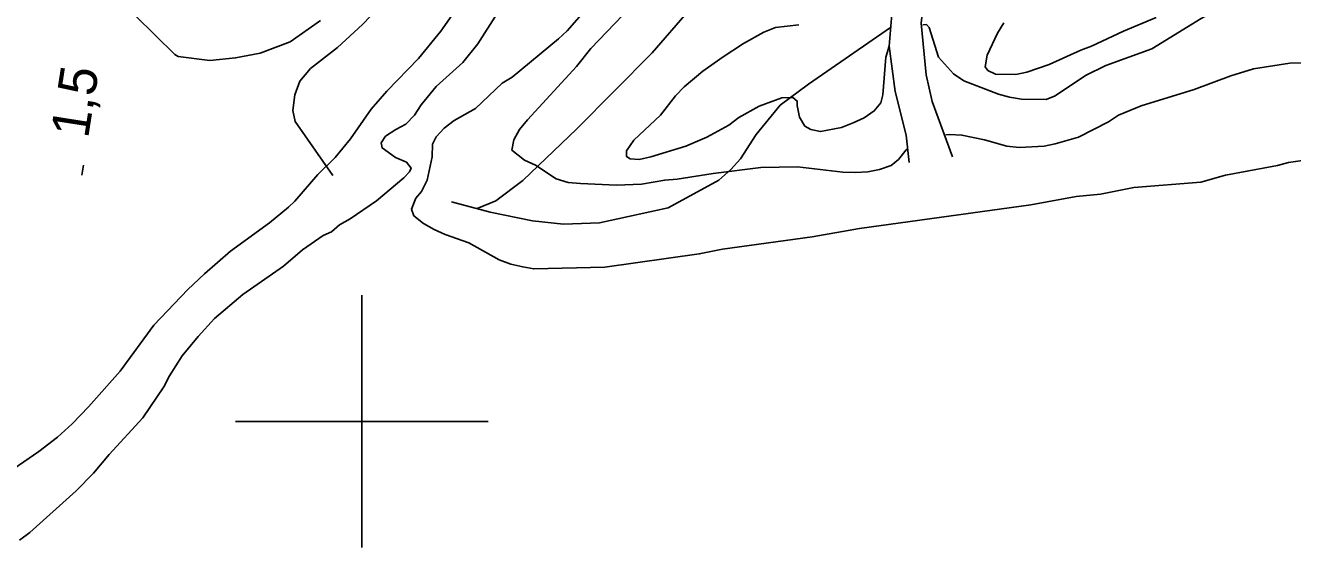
# Model space of a CAD drawing. Extents: x 282461 to 284471, y 5554090 to 5557646.
# Drawn here: x 282973.4 to 283073.7, y 5554590 to 5554631.3 of the extents above; entities that cross this region are included whole.
import ezdxf

# ---------------------------------------------------------------- set-up
doc = ezdxf.new("R2010")
doc.units = 0
for name, color, linetype in [('Niveau 19', 7, 'Continuous'), ('Niveau 2', 7, 'Continuous'), ('Niveau 22', 7, 'Continuous'), ('Niveau 3', 7, 'Continuous'), ('Niveau 4', 7, 'Continuous'), ('Niveau 61', 7, 'Continuous')]:
    doc.layers.add(name, color=color, linetype=linetype)

msp = doc.modelspace()

# ---------------------------------------------------------------- linework, layer by layer
at = {"layer": 'Niveau 19'}
for points in [[(283068.06, 5554712.51), (283063.46, 5554707.21), (283055.84, 5554697.45), (283052.31, 5554692.63), (283048.44, 5554688.04), (283043.95, 5554683.22), (283041.39, 5554680.04), (283038.21, 5554675.64), (283035.71, 5554672.46), (283032.03, 5554667.89), (283028.04, 5554663.47), (283020.37, 5554653.48), (283012.4, 5554644.31), (283000.04, 5554631.42), (282998.06, 5554629.6), (282995.94, 5554627.94), (282995.09, 5554626.94), (282994.7, 5554625.84), (282994.55, 5554624.62), (282994.72, 5554623.73), (282997.7, 5554619.47)], [(283103.3, 5554710.23), (283094.06, 5554697.21), (283089.32, 5554691.96), (283085.62, 5554687.44), (283080.84, 5554681.32), (283077.36, 5554677.32), (283075.87, 5554675.79), (283069.49, 5554668.61), (283064.87, 5554664.36), (283060.8, 5554660.17), (283053.44, 5554652.98), (283049.9, 5554649.91), (283046.8, 5554647), (283044.52, 5554644.42), (283043.56, 5554642.72), (283042.42, 5554637.95), (283041.73, 5554629.69), (283042.2, 5554626.11), (283043.06, 5554622.65), (283043.31, 5554620.49)], [(283046.73, 5554620.95), (283045.12, 5554625.31), (283044.66, 5554627.42), (283044.25, 5554631.52), (283044.78, 5554636.43), (283045.42, 5554638.98), (283045.97, 5554640.73), (283046.75, 5554642.6), (283049.01, 5554646.11), (283053.42, 5554650.48), (283056.64, 5554653.39), (283060.57, 5554656.74), (283066.45, 5554662.75), (283069.43, 5554665.65), (283072.35, 5554668.02), (283073.89, 5554669.37)], [(282996.73, 5554631.72), (282994.32, 5554630.05), (282991.96, 5554629.15), (282990, 5554628.77), (282987.97, 5554628.56), (282985.47, 5554628.87), (282985.19, 5554629.05), (282982.09, 5554632.09)]]:
    msp.add_lwpolyline(points, dxfattribs=at)
at = {"layer": 'Niveau 2'}
for points in [[(283023.82, 5554635.47), (283018.12, 5554629.51), (283016.98, 5554628.1), (283013.1, 5554623.86), (283012.48, 5554623.1), (283012.03, 5554622.28), (283011.87, 5554621.47), (283012.86, 5554620.67), (283013.74, 5554620.28), (283015.38, 5554619.2), (283016.32, 5554618.92), (283017.3, 5554618.82), (283020.15, 5554618.69), (283022.12, 5554618.78), (283023.97, 5554619.1), (283024.96, 5554619.17), (283027.79, 5554619.63), (283031.56, 5554620.09), (283034.46, 5554620.14), (283038.06, 5554619.73), (283039.05, 5554619.69), (283040.04, 5554619.76), (283040.96, 5554619.95), (283041.89, 5554620.25), (283042.46, 5554620.72), (283043.08, 5554621.49), (283043.16, 5554621.56)], [(283044.38, 5554631.38), (283044.67, 5554631.42), (283044.9, 5554631.19), (283045.64, 5554628.83), (283046.82, 5554627.51), (283047.64, 5554626.95), (283050.38, 5554625.89), (283051.26, 5554625.67), (283052.19, 5554625.51), (283054.16, 5554625.48), (283054.85, 5554625.78), (283057.26, 5554627.39), (283058.87, 5554628.16), (283062.5, 5554629.5), (283066.41, 5554631.88), (283068.13, 5554632.83), (283069.05, 5554633.2), (283070.96, 5554633.52), (283073.92, 5554633.85)], [(282970.42, 5554594.88), (282974.43, 5554597.61), (282975.92, 5554598.74), (282977.07, 5554599.8), (282978.38, 5554601.16), (282980.88, 5554603.98), (282983.55, 5554607.62), (282986.23, 5554610.45), (282987.54, 5554611.69), (282989.6, 5554613.46), (282992.7, 5554615.71), (282994.19, 5554616.95), (282994.7, 5554617.43), (282996.52, 5554619.54), (282997.89, 5554620.9), (282999.09, 5554622.37), (283000.73, 5554624.72), (283001.98, 5554626.13), (283004.49, 5554628.72), (283006.26, 5554630.9), (283007.5, 5554632.66)], [(283050.81, 5554631.56), (283050.31, 5554630.74), (283049.47, 5554628.99), (283049.31, 5554628.06), (283049.54, 5554627.77), (283050.13, 5554627.49), (283051.75, 5554627.46), (283052.62, 5554627.65), (283054.4, 5554628.26), (283056.88, 5554629.39), (283057.74, 5554629.7), (283060.27, 5554630.9), (283062.86, 5554631.98)], [(283034.58, 5554631.38), (283032.73, 5554631.18), (283031.8, 5554630.82), (283030.2, 5554629.92), (283028.59, 5554628.85), (283026.98, 5554627.72), (283025.5, 5554626.48), (283024.81, 5554625.78), (283023.62, 5554624.25), (283021.51, 5554622.25), (283020.94, 5554621.42), (283020.95, 5554620.96), (283021.24, 5554620.79), (283021.94, 5554620.74), (283022.86, 5554620.93), (283025.63, 5554621.79), (283027.3, 5554622.51), (283029.03, 5554623.46), (283029.83, 5554624.06), (283031.44, 5554624.95), (283033.22, 5554625.62), (283034.09, 5554625.63), (283034.45, 5554625.35), (283034.45, 5554625), (283034.64, 5554624.07), (283035.06, 5554623.38), (283035.53, 5554623.1), (283036.28, 5554622.94), (283037.96, 5554623.26), (283038.88, 5554623.62), (283039.74, 5554624.04), (283040.55, 5554624.57), (283041.06, 5554625.22), (283041.22, 5554625.86), (283041.46, 5554628.82), (283041.72, 5554629.69)], [(283046.2, 5554622.68), (283046.49, 5554622.7), (283047.48, 5554622.66), (283049.28, 5554622.28), (283051.03, 5554621.79), (283052.02, 5554621.69), (283053.99, 5554621.78), (283054.86, 5554621.96), (283056.71, 5554622.51), (283059.07, 5554623.71), (283059.87, 5554624.25), (283061.66, 5554624.97), (283065.87, 5554626.26), (283068.76, 5554627.35), (283070.55, 5554627.9), (283073.44, 5554628.35), (283077.1, 5554628.41)]]:
    msp.add_lwpolyline(points, dxfattribs=at)
at = {"layer": 'Niveau 22'}
for points in [[(283009.13, 5554616.84), (283010.6, 5554617.46), (283012.74, 5554619.07), (283017, 5554623.16), (283022.96, 5554629.18), (283028.84, 5554635.96), (283031.12, 5554638.37), (283033.17, 5554640.78), (283035.83, 5554644.6), (283038.1, 5554647.53), (283041.12, 5554651.18), (283044.66, 5554654.6), (283053.08, 5554660.53), (283058.06, 5554662.89), (283065.34, 5554666.1), (283067.64, 5554666.91)], [(283041.84, 5554631.17), (283035.35, 5554626.7), (283033.1, 5554625.02), (283031.19, 5554622.7), (283029.95, 5554620.78), (283029.19, 5554619.95), (283028.26, 5554619.1), (283024.24, 5554616.91), (283018.8, 5554615.72), (283015.96, 5554615.62), (283013.51, 5554615.87), (283010.14, 5554616.57), (283007.08, 5554617.38)]]:
    msp.add_lwpolyline(points, dxfattribs=at)
at = {"layer": 'Niveau 3'}
msp.add_line((282977.85, 5554619.5), (282977.97, 5554620.29), dxfattribs=at)
at = {"layer": 'Niveau 4'}
for points in [[(283019.23, 5554612.21), (283013.6, 5554612.07), (283012.73, 5554612.23), (283011.79, 5554612.45), (283010.86, 5554612.78), (283008.46, 5554614.14), (283006.59, 5554614.8), (283005.71, 5554615.2), (283004.89, 5554615.65), (283004.12, 5554616.28), (283003.94, 5554616.8), (283004.28, 5554617.67), (283004.73, 5554618.2), (283005.18, 5554619.08), (283005.56, 5554620.94), (283005.6, 5554621.93), (283005.88, 5554622.52), (283006.51, 5554623.22), (283007.31, 5554623.82), (283008.98, 5554624.77), (283011.09, 5554626.78), (283011.9, 5554627.26), (283015.56, 5554630.27), (283016.25, 5554630.92), (283017.96, 5554632.87)], [(283010.71, 5554632.29), (283009.18, 5554629.88), (283007.99, 5554628.41), (283005.87, 5554626.52), (283004.68, 5554625.05), (283004.17, 5554624.23), (283003.48, 5554623.52), (283002.68, 5554623.11), (283001.87, 5554622.57), (283001.53, 5554622.04), (283001.6, 5554621.64), (283002.66, 5554620.9), (283003.53, 5554620.51), (283003.89, 5554620.05), (283003.78, 5554619.75), (283003.32, 5554619.28), (283001.15, 5554617.45), (282999.08, 5554616.02), (282998.22, 5554615.55), (282997.59, 5554615.01), (282996.95, 5554614.71), (282995.29, 5554613.58), (282993.8, 5554612.28), (282990.59, 5554610.03), (282988.35, 5554608.13), (282987.04, 5554606.72), (282985.79, 5554605.19), (282984.77, 5554603.61), (282984.32, 5554602.73), (282982.68, 5554600.27), (282980, 5554597.38), (282978.75, 5554595.91), (282977.38, 5554594.49), (282973.72, 5554591.19)], [(283077.03, 5554621.01), (283073.33, 5554620.49), (283072.46, 5554620.25), (283068.35, 5554619.48), (283066.38, 5554618.93), (283061.1, 5554618.5), (283058.44, 5554617.99), (283056.53, 5554617.79), (283052.94, 5554617.15), (283039.38, 5554615.26), (283035.62, 5554614.62), (283028.55, 5554613.64), (283026.7, 5554613.26), (283019.23, 5554612.21)], [(282973.72, 5554591.19), (282972.91, 5554590.59)]]:
    msp.add_lwpolyline(points, dxfattribs=at)
at = {"layer": 'Niveau 61'}
for points in [[(283000, 5554590), (283000, 5554610)], [(282990, 5554600), (283010, 5554600)]]:
    msp.add_lwpolyline(points, dxfattribs=at)

# ---------------------------------------------------------------- texts
at = {"layer": 'Niveau 3'}
msp.add_text('1,5  ', height=3, rotation=81.0957, dxfattribs=at).set_placement((282978.33, 5554622.34))

doc.saveas('drawing.dxf')
